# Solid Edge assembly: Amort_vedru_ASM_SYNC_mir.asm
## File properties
Author: KULL
Template: Iso Metric Assembly.asm
Last saved by: KULL
Revision: 3
Application: Solid Edge
Username: KULL
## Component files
Amort_sync.par
vedru__sync_mir.par
Amort_vedru_ASM_SYNC.asm
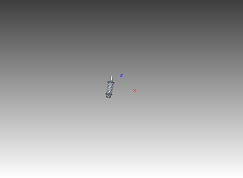
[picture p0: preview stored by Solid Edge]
